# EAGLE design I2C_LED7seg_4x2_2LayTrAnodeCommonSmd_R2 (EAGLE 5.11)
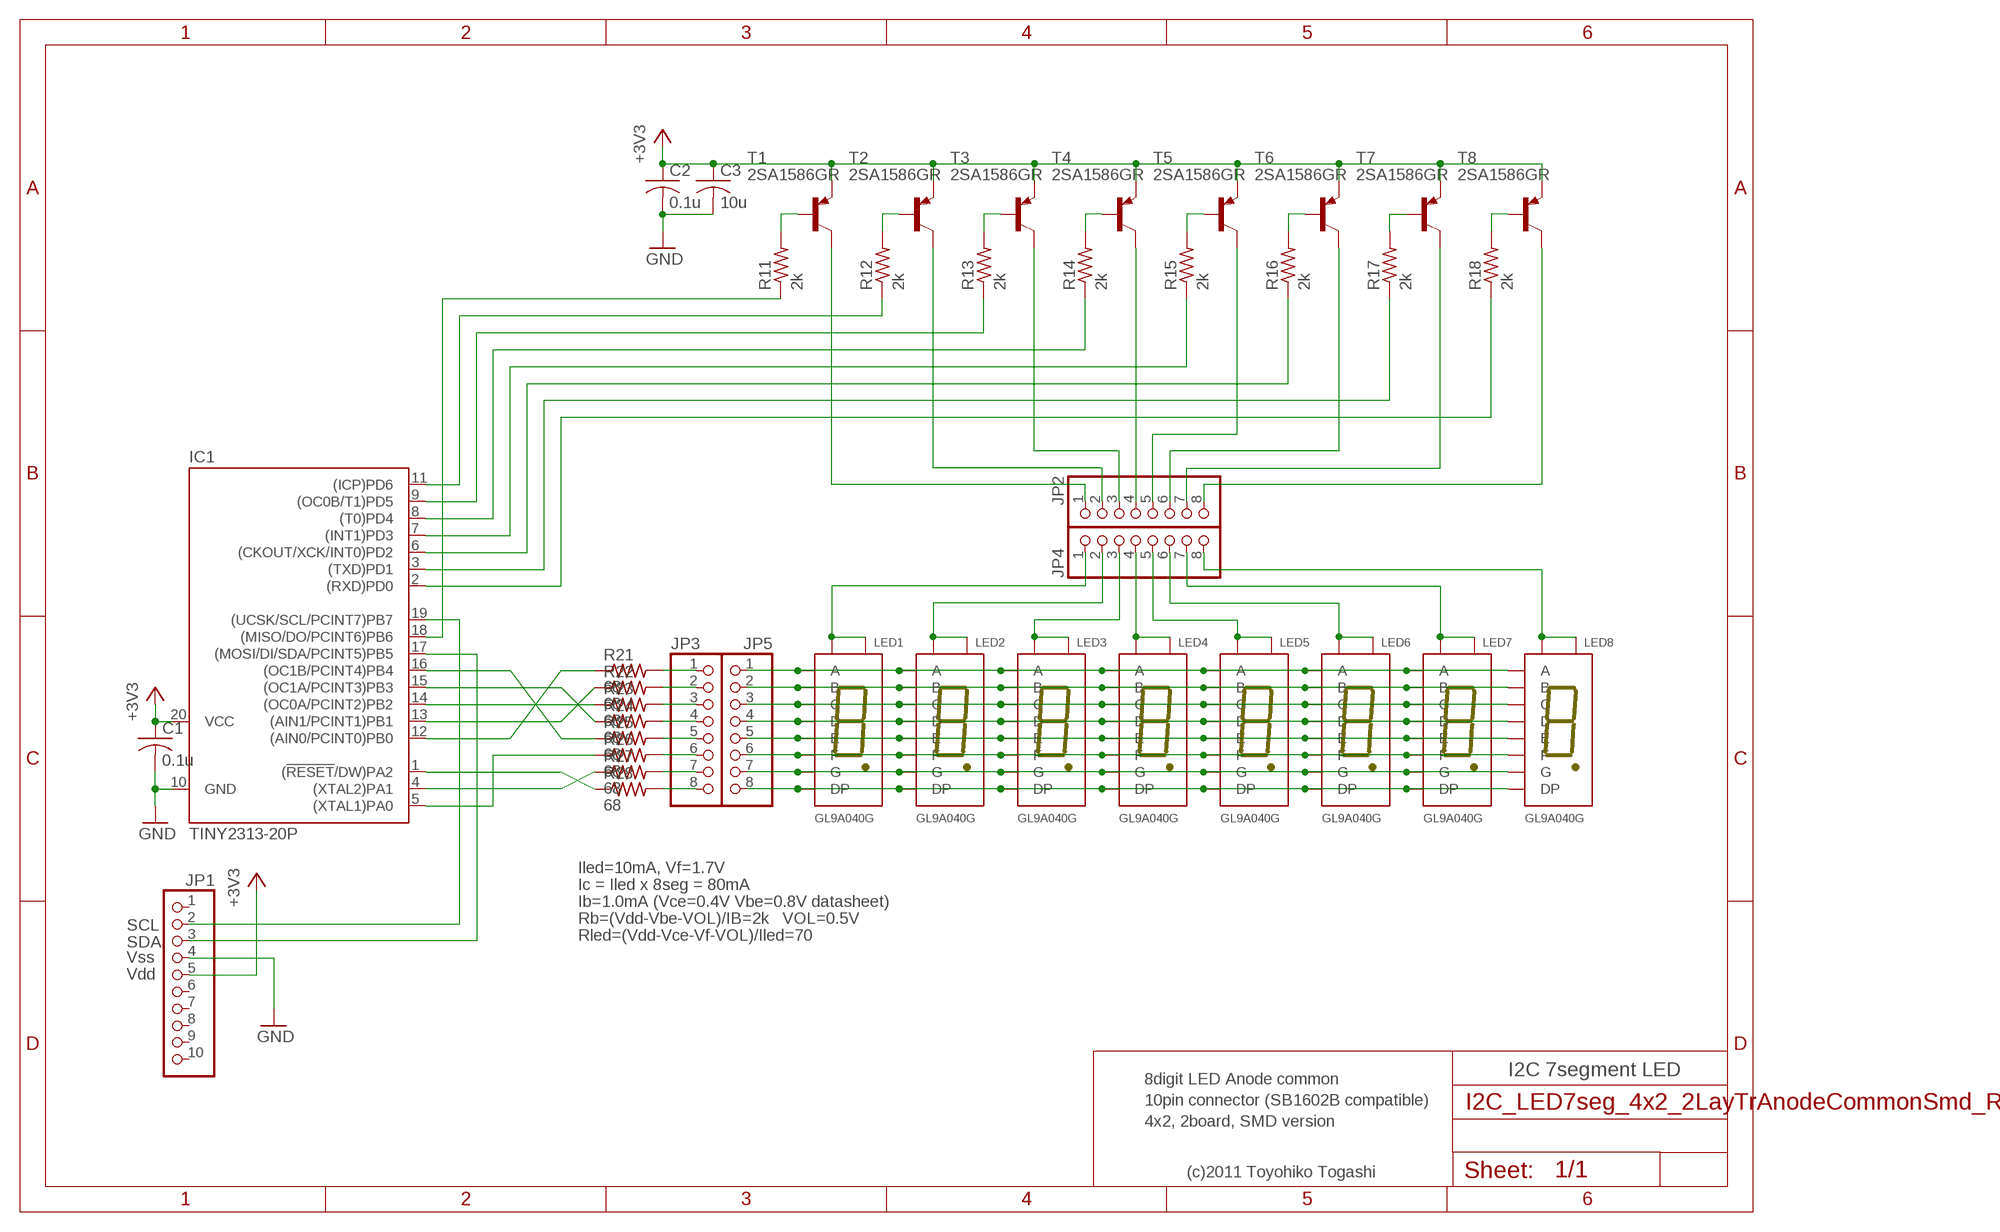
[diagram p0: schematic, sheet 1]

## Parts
C1  0.1u  C-USC0603  [C0603]
C2  0.1u  C-USC0603  [C0603]
C3  10u  C-USC1206  [C1206]
IC1  TINY2313-20P  [DIL20]
JP1  PINHD-1X10  [1X10]
JP2  PINHD-1X8  [1X08]
JP3  PINHD-1X8  [1X08]
JP4  PINHD-1X8  [1X08]
JP5  PINHD-1X8  [1X08]
LED1  GL9A040G  [GL9A040G]
LED2  GL9A040G  [GL9A040G]
LED3  GL9A040G  [GL9A040G]
LED4  GL9A040G  [GL9A040G]
LED5  GL9A040G  [GL9A040G]
LED6  GL9A040G  [GL9A040G]
LED7  GL9A040G  [GL9A040G]
LED8  GL9A040G  [GL9A040G]
R11  2k  R-US_R0603  [R0603]
R12  2k  R-US_R0603  [R0603]
R13  2k  R-US_R0603  [R0603]
R14  2k  R-US_R0603  [R0603]
R15  2k  R-US_R0603  [R0603]
R16  2k  R-US_R0603  [R0603]
R17  2k  R-US_R0603  [R0603]
R18  2k  R-US_R0603  [R0603]
R21  68  R-US_R0603  [R0603]
R22  68  R-US_R0603  [R0603]
R23  68  R-US_R0603  [R0603]
R24  68  R-US_R0603  [R0603]
R25  68  R-US_R0603  [R0603]
R26  68  R-US_R0603  [R0603]
R27  68  R-US_R0603  [R0603]
R28  68  R-US_R0603  [R0603]
T1  2SA1586GR  BC807-16LT1-PNP-SOT23-BEC  [SOT23-BEC]
T2  2SA1586GR  BC807-16LT1-PNP-SOT23-BEC  [SOT23-BEC]
T3  2SA1586GR  BC807-16LT1-PNP-SOT23-BEC  [SOT23-BEC]
T4  2SA1586GR  BC807-16LT1-PNP-SOT23-BEC  [SOT23-BEC]
T5  2SA1586GR  BC807-16LT1-PNP-SOT23-BEC  [SOT23-BEC]
T6  2SA1586GR  BC807-16LT1-PNP-SOT23-BEC  [SOT23-BEC]
T7  2SA1586GR  BC807-16LT1-PNP-SOT23-BEC  [SOT23-BEC]
T8  2SA1586GR  BC807-16LT1-PNP-SOT23-BEC  [SOT23-BEC]

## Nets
+3V3: C1.1 C2.1 C3.1 IC1.20(VCC) JP1.5 T1.E T2.E T3.E T4.E T5.E T6.E T7.E T8.E
GND: C1.2 C2.2 C3.2 IC1.10(GND) JP1.4
N$1: JP3.7 R27.2
N$2: JP3.8 R28.2
N$3: IC1.19((UCSK/SCL/PCINT7)PB7) JP1.2
N$4: IC1.17((MOSI/DI/SDA/PCINT5)PB5) JP1.3
N$5: JP3.1 R21.2
N$6: JP3.2 R22.2
N$7: JP3.3 R23.2
N$8: JP3.4 R24.2
N$9: JP3.5 R25.2
N$10: JP3.6 R26.2
N$11: JP2.1 T1.C
N$12: JP2.2 T2.C
N$13: R18.2 T8.B
N$14: IC1.5((XTAL1)PA0) R26.1
N$15: IC1.4((XTAL2)PA1) R27.1
N$16: IC1.1((!RESET!/DW)PA2) R28.1
N$17: IC1.12((AIN0/PCINT0)PB0) R21.1
N$18: JP4.1 LED1.P$1(CA1) LED1.P$6(CA6)
N$19: IC1.13((AIN1/PCINT1)PB1) R22.1
N$20: IC1.14((OC0A/PCINT2)PB2) R23.1
N$21: IC1.15((OC1A/PCINT3)PB3) R24.1
N$22: IC1.16((OC1B/PCINT4)PB4) R25.1
N$23: JP4.2 LED2.P$1(CA1) LED2.P$6(CA6)
N$24: JP4.3 LED3.P$1(CA1) LED3.P$6(CA6)
N$25: IC1.2((RXD)PD0) R18.1
N$26: R11.2 T1.B
N$27: JP4.4 LED4.P$1(CA1) LED4.P$6(CA6)
N$28: IC1.18((MISO/DO/PCINT6)PB6) R11.1
N$29: JP4.5 LED5.P$1(CA1) LED5.P$6(CA6)
N$30: JP4.6 LED6.P$1(CA1) LED6.P$6(CA6)
N$31: JP4.7 LED7.P$1(CA1) LED7.P$6(CA6)
N$32: JP4.8 LED8.P$1(CA1) LED8.P$6(CA6)
N$33: JP2.3 T3.C
N$34: JP2.4 T4.C
N$35: R17.2 T7.B
N$36: JP2.5 T5.C
N$37: JP2.6 T6.C
N$38: JP2.7 T7.C
N$39: JP2.8 T8.C
N$40: JP5.1 LED1.P$10(A) LED2.P$10(A) LED3.P$10(A) LED4.P$10(A) LED5.P$10(A) LED6.P$10(A) LED7.P$10(A) LED8.P$10(A)
N$41: JP5.2 LED1.P$9(B) LED2.P$9(B) LED3.P$9(B) LED4.P$9(B) LED5.P$9(B) LED6.P$9(B) LED7.P$9(B) LED8.P$9(B)
N$42: JP5.3 LED1.P$8(C) LED2.P$8(C) LED3.P$8(C) LED4.P$8(C) LED5.P$8(C) LED6.P$8(C) LED7.P$8(C) LED8.P$8(C)
N$43: JP5.4 LED1.P$5(D) LED2.P$5(D) LED3.P$5(D) LED4.P$5(D) LED5.P$5(D) LED6.P$5(D) LED7.P$5(D) LED8.P$5(D)
N$44: JP5.5 LED1.P$4(E) LED2.P$4(E) LED3.P$4(E) LED4.P$4(E) LED5.P$4(E) LED6.P$4(E) LED7.P$4(E) LED8.P$4(E)
N$45: JP5.6 LED1.P$2(F) LED2.P$2(F) LED3.P$2(F) LED4.P$2(F) LED5.P$2(F) LED6.P$2(F) LED7.P$2(F) LED8.P$2(F)
N$46: JP5.7 LED1.P$3(G) LED2.P$3(G) LED3.P$3(G) LED4.P$3(G) LED5.P$3(G) LED6.P$3(G) LED7.P$3(G) LED8.P$3(G)
N$47: JP5.8 LED1.P$7(DP) LED2.P$7(DP) LED3.P$7(DP) LED4.P$7(DP) LED5.P$7(DP) LED6.P$7(DP) LED7.P$7(DP) LED8.P$7(DP)
N$48: R16.2 T6.B
N$60: R15.2 T5.B
N$72: R14.2 T4.B
N$84: R13.2 T3.B
N$96: R12.2 T2.B
N$98: IC1.3((TXD)PD1) R17.1
N$99: IC1.6((CKOUT/XCK/INT0)PD2) R16.1
N$100: IC1.7((INT1)PD3) R15.1
N$101: IC1.8((T0)PD4) R14.1
N$102: IC1.9((OC0B/T1)PD5) R13.1
N$103: IC1.11((ICP)PD6) R12.1
Unconnected: JP1.1 JP1.6 JP1.7 JP1.8 JP1.9 JP1.10

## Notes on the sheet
- Iled=10mA, Vf=1.7V
- Ic = Iled x 8seg = 80mA
- Ib=1.0mA (Vce=0.4V Vbe=0.8V datasheet)
- Rb=(Vdd-Vbe-VOL)/IB=2k   VOL=0.5V
- SCL
- Rled=(Vdd-Vce-Vf-VOL)/Iled=70
- SDA
- Vss
- Vdd
- I2C 7segment LED
- 8digit LED Anode common
- 10pin connector (SB1602B compatible)
- 4x2, 2board, SMD version
- (c)2011 Toyohiko Togashi

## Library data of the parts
C1-C3 = rcl:C-US: CAPACITOR, American symbol
IC1 = TOG:TINY2313: 8-bit AVR Microcontroller with 2K Bytes Flash Source: http://www.atmel.com .. doc2543.pdf
JP1 = pinhead:PINHD-1X10: PIN HEADER
JP2-JP5 = pinhead:PINHD-1X8: PIN HEADER
LED1-LED8 = TOG:GL9A040G: 7 Segment LED
R11-R18 R21-R28 = rcl:R-US_: RESISTOR, American symbol
T1-T8 = transistor:*-PNP-: PNP Transistror

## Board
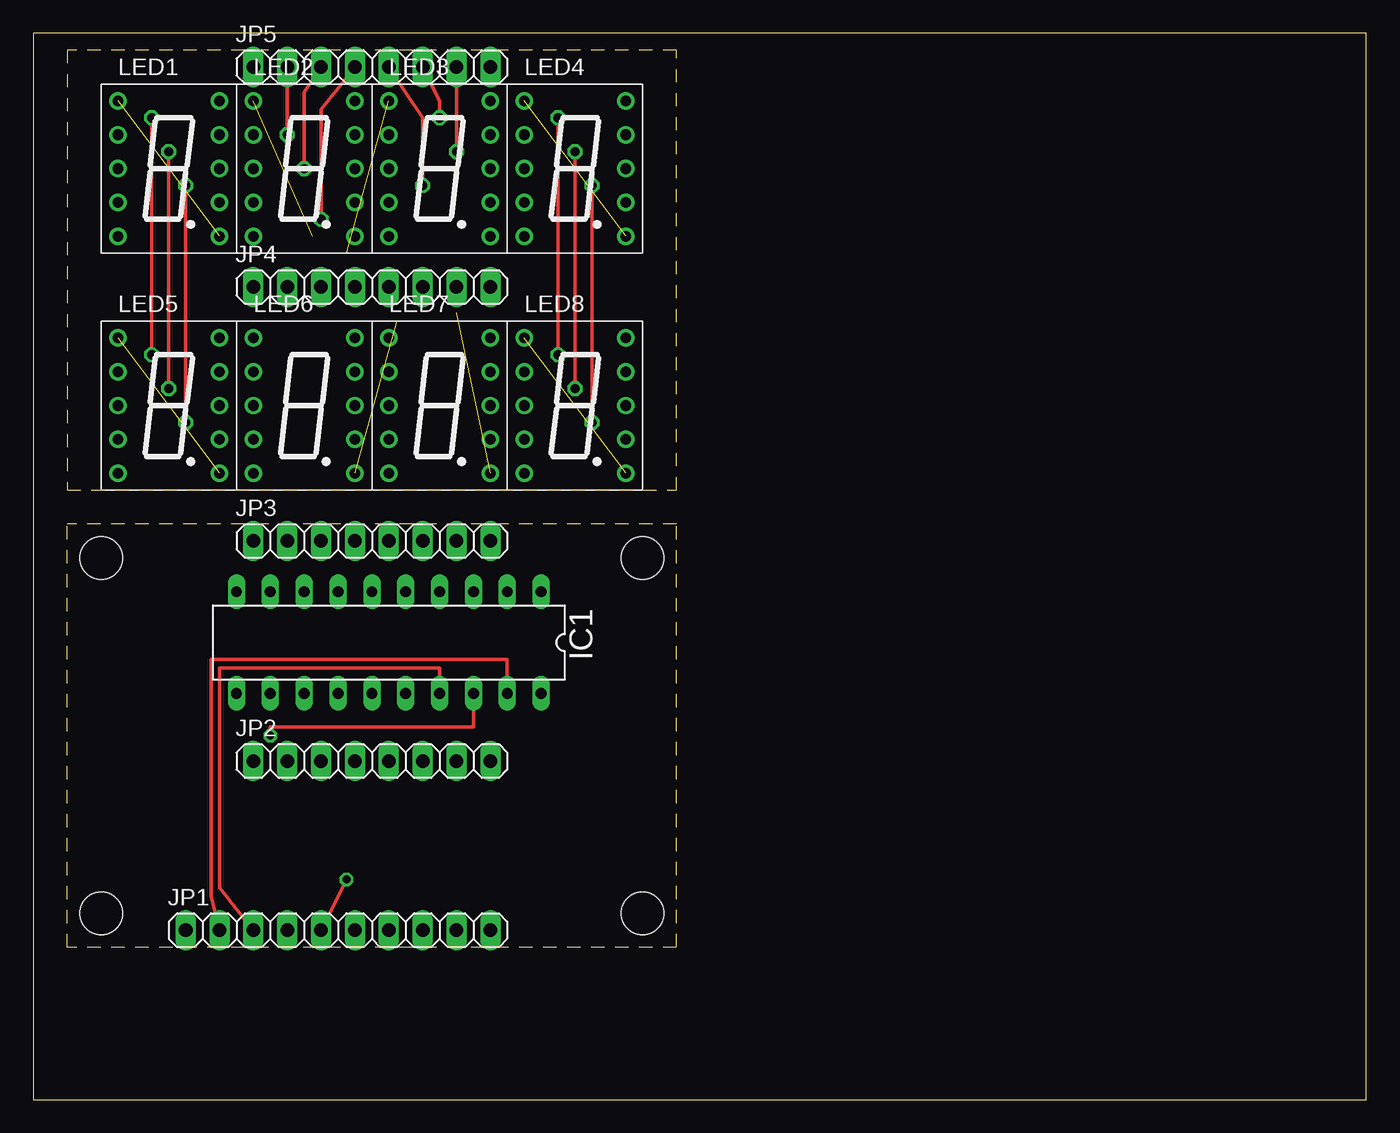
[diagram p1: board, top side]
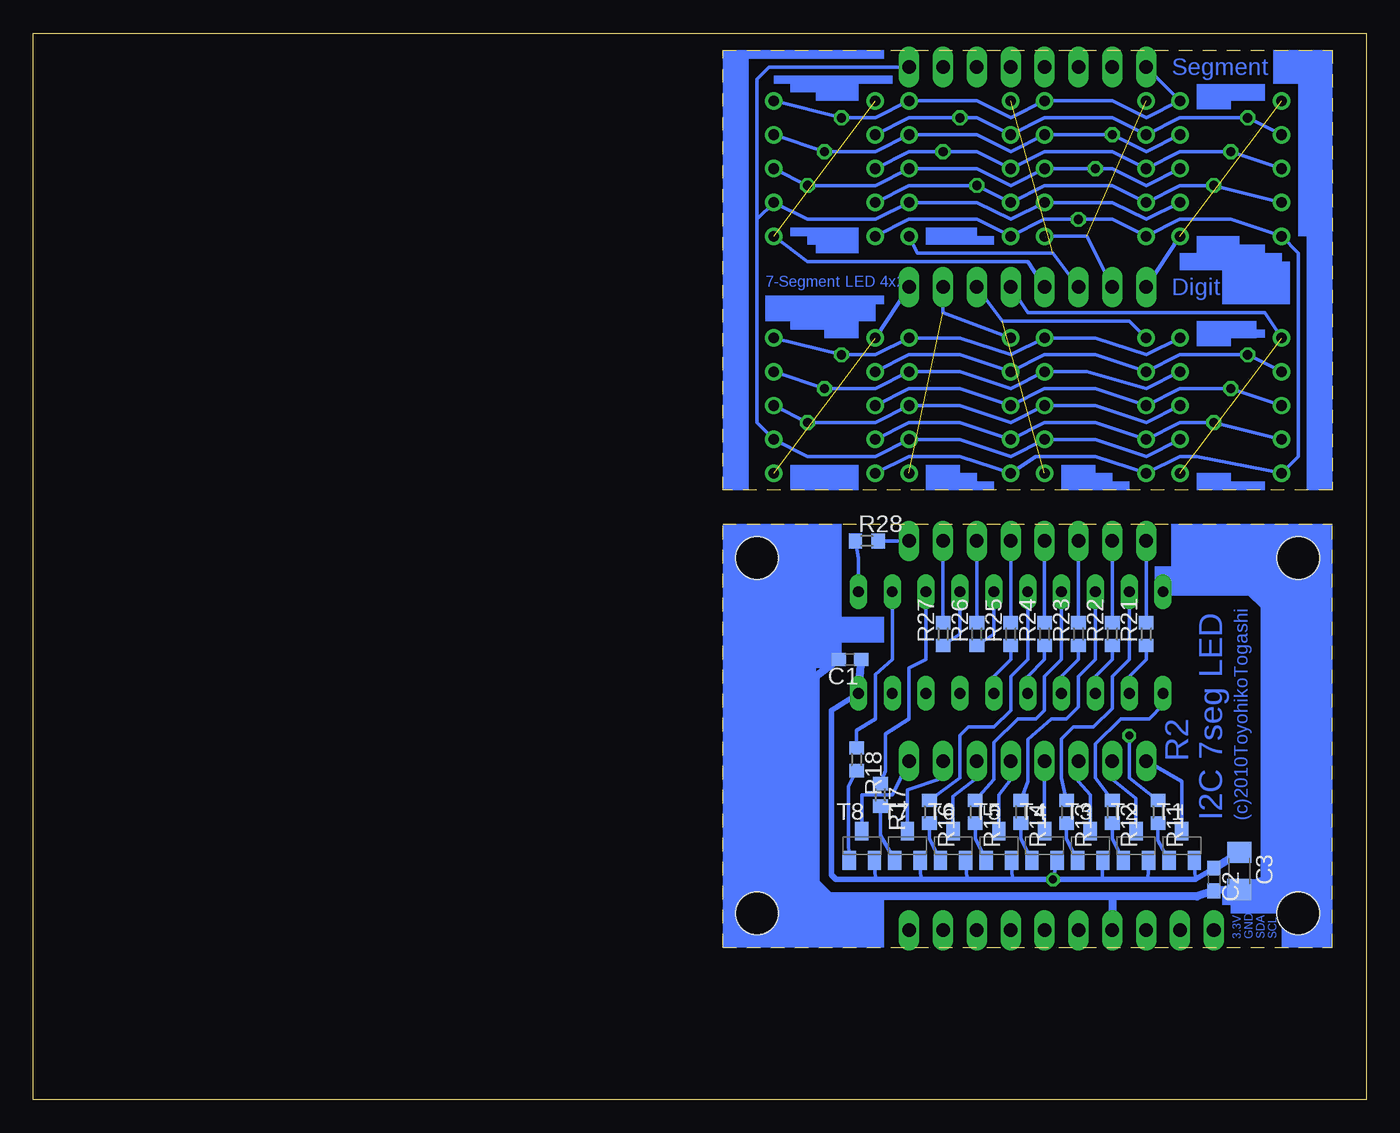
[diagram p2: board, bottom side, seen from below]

Size 100 x 80 mm. Coordinates in mm from the lower left corner, seen from the top.
Outline: 0,0 100,0 100,80 0,80 0,0
Outline: 2.54,78.74 2.54,45.72 48.26,45.72 48.26,78.74 2.54,78.74
Outline: 48.26,43.18 2.54,43.18 2.54,11.43 48.26,11.43 48.26,43.18
Copper layers (1*16): Top 0.035mm / dielectric 1.5mm / Bottom 0.035mm
Design rules "default": minimum track width 10mil, minimum drill 24mil, track to track 8mil, track to pad 8mil, pad to pad 8mil, via to via 8mil, smd to smd 8mil, copper to edge 40mil, drill to drill 8mil, minimum pad ring 10mil, minimum via ring 8mil, stop-mask expansion 4mil, vias tented up to drill 0mil, thermal gap 10mil
Holes 3.2 mm at 5.08,40.64 45.72,40.64 45.72,13.97 5.08,13.97

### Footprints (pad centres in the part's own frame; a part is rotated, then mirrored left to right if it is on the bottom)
C0603 = smd 1.1 x 1: 1 -0.85,0; 2 0.85,0
C1206 = smd 1.6 x 1.8: 1 -1.4,0; 2 1.4,0
DIL20 = drill 0.813 long: 1 -11.43,-3.81; 2 -8.89,-3.81; 3 -6.35,-3.81; 4 -3.81,-3.81; 5 -1.27,-3.81; 6 1.27,-3.81; 7 3.81,-3.81; 8 6.35,-3.81; 9 8.89,-3.81; 10 11.43,-3.81; 11 11.43,3.81; 12 8.89,3.81; 13 6.35,3.81; 14 3.81,3.81; 15 1.27,3.81; 16 -1.27,3.81; 17 -3.81,3.81; 18 -6.35,3.81; 19 -8.89,3.81; 20 -11.43,3.81
1X10 = drill 1.016 long: 1 -11.43,0; 2 -8.89,0; 3 -6.35,0; 4 -3.81,0; 5 -1.27,0; 6 1.27,0; 7 3.81,0; 8 6.35,0; 9 8.89,0; 10 11.43,0
1X08 = drill 1.016 long: 1 -8.89,0; 2 -6.35,0; 3 -3.81,0; 4 -1.27,0; 5 1.27,0; 6 3.81,0; 7 6.35,0; 8 8.89,0
GL9A040G = drill 0.8 round: P$1 -3.81,5.08; P$2 -3.81,2.54; P$3 -3.81,0; P$4 -3.81,-2.54; P$5 -3.81,-5.08; P$6 3.81,-5.08; P$7 3.81,-2.54; P$8 3.81,0; P$9 3.81,2.54; P$10 3.81,5.08
R0603 = smd 1 x 1.1: 1 -0.85,0; 2 0.85,0
SOT23-BEC = smd 1 x 1.4: B -0.95,-1.1; C 0,1.1; E 0.95,-1.1

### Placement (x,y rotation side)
C1  38.73,33.02 180 bottom
C2  11.43,16.51 270 bottom
C3  9.53,17.14 270 bottom
IC1  26.67,34.29 180 top
JP1  22.86,12.7 0 top
JP2  25.4,25.4 0 top
JP3  25.4,41.91 0 top
JP4  25.4,60.96 0 top
JP5  25.4,77.47 0 top
LED1  10.16,69.85 0 top
LED2  20.32,69.85 0 top
LED3  30.48,69.85 0 top
LED4  40.64,69.85 0 top
LED5  10.16,52.07 0 top
LED6  20.32,52.07 0 top
LED7  30.48,52.07 0 top
LED8  40.64,52.07 0 top
R11  15.62,21.59 270 bottom
R12  19.05,21.59 270 bottom
R13  22.48,21.59 270 bottom
R14  25.91,21.59 270 bottom
R15  29.34,21.59 270 bottom
R16  32.77,21.59 270 bottom
R17  36.45,22.86 270 bottom
R18  38.23,25.53 270 bottom
R21  16.51,34.92 90 bottom
R22  19.05,34.92 90 bottom
R23  21.59,34.92 90 bottom
R24  24.13,34.92 90 bottom
R25  26.67,34.92 90 bottom
R26  29.21,34.92 90 bottom
R27  31.75,34.92 90 bottom
R28  37.47,41.91 0 bottom
T1  13.84,19.05 0 bottom
T2  17.27,19.05 0 bottom
T3  20.7,19.05 0 bottom
T4  24.13,19.05 0 bottom
T5  27.56,19.05 0 bottom
T6  30.99,19.05 0 bottom
T7  34.42,19.05 0 bottom
T8  37.85,19.05 0 bottom

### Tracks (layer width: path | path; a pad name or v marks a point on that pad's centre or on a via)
+3V3  (via drill 0.6)
  Top 0.254: v23.5,16.51 JP1.5
  Bottom 0.254: 12.83,16.51 T1.E | 16.38,16.51 T2.E | 19.81,16.51 T3.E | v23.5,16.51 T4.E | 36.83,16.51 T8.E | 33.4,16.51 T7.E | 26.54,16.51 T5.E | 29.97,16.51 T6.E
  Bottom 0.406: IC1.20 40.13,29.21 40.13,16.87 39.77,16.51 36.83,16.51 33.4,16.51 29.97,16.51 26.54,16.51 v23.5,16.51 19.81,16.51 16.38,16.51 12.83,16.51 C2.1
  Bottom 0.61: IC1.20 C1.1 | C2.1 C3.1
GND
  Bottom 0.61: 19.05,15.24 40.25,15.24 41.27,16.26 41.27,31.75 C1.2 | 19.05,15.24 JP1.4 | IC1.10 8.7,38.1 7.62,37.02 7.62,16.51 C3.2 8.89,15.88 C2.2 12.7,15.24 19.05,15.24
N$1
  Bottom 0.254: JP3.7 R27.2
N$2
  Bottom 0.254: JP3.8 R28.2
N$3
  Top 0.254: JP1.2 13.34,15.24 13.34,33.02 35.56,33.02 IC1.19
N$4
  Top 0.254: JP1.3 13.97,15.88 13.97,32.38 30.48,32.38 IC1.17
N$5
  Bottom 0.254: JP3.1 R21.2
N$6
  Bottom 0.254: JP3.2 R22.2
N$7
  Bottom 0.254: JP3.3 R23.2
N$8
  Bottom 0.254: JP3.4 R24.2
N$9
  Bottom 0.254: JP3.5 R25.2
N$10
  Bottom 0.254: JP3.6 R26.2
N$11
  Bottom 0.254: T1.C 13.84,23.88 JP2.1
N$12
  Bottom 0.254: T2.C 17.27,22.61 19.05,24 JP2.2
N$13
  Bottom 0.254: T8.B 38.86,19.68 38.86,23.5 R18.2
N$14
  Bottom 0.254: IC1.5 27.94,34.92 R26.1
N$15
  Bottom 0.254: IC1.4 30.48,34.92 R27.1
N$16
  Bottom 0.254: R28.1 38.1,40.64 IC1.1
N$17
  Bottom 0.254: IC1.12 17.78,31.75 16.51,33.02 R21.1
N$18  (1 unrouted)
  Bottom 0.254: JP4.1 LED1.P$6
N$19
  Bottom 0.254: IC1.13 20.32,31.75 19.05,33.02 R22.1
N$20
  Bottom 0.254: IC1.14 22.86,31.75 21.59,33.02 R23.1
N$21
  Bottom 0.254: IC1.15 25.4,31.75 24.13,33.02 R24.1
N$22
  Bottom 0.254: IC1.16 27.94,31.75 26.67,33.02 R25.1
N$23  (1 unrouted)
  Bottom 0.254: JP4.2 20.95,64.77 LED2.P$6
N$24  (1 unrouted)
  Bottom 0.254: JP4.3 23.5,63.5 33.66,63.5 LED3.P$6
N$25
  Bottom 0.254: IC1.2 35.56,33.02 36.83,31.88 36.83,28.57 38.23,27.69 R18.1
N$26
  Bottom 0.254: T1.B 15.62,19.43 R11.2
N$27  (1 unrouted)
  Bottom 0.254: JP4.4 25.4,62.87 41.91,62.87 LED4.P$6
N$28  (via drill 0.6)
  Top 0.254: v17.78,27.3 17.78,27.94 33.02,27.94 IC1.18
  Bottom 0.254: R11.1 17.78,24.13 v17.78,27.3
N$29  (1 unrouted)
  Bottom 0.254: JP4.5 25.4,59.05 7.62,59.05 LED5.P$1
N$30  (1 unrouted)
  Bottom 0.254: JP4.6 27.3,58.42 17.78,58.42 LED6.P$1
N$31  (1 unrouted)
  Bottom 0.254: JP4.7 31.75,59.05 LED7.P$1
N$32  (1 unrouted)
  Bottom 0.254: LED8.P$1 JP4.8
N$33
  Bottom 0.254: T3.C 20.7,22.86 21.59,23.88 JP2.3
N$34
  Bottom 0.254: T4.C JP2.4
N$35
  Bottom 0.254: T7.B 36.45,19.81 R17.2
N$36
  Bottom 0.254: T5.C 27.56,22.86 26.67,24 JP2.5
N$37
  Bottom 0.254: T6.C 30.99,22.73 29.21,24.13 JP2.6
N$38
  Bottom 0.254: T7.C 34.42,23.24 31.75,24.13 JP2.7
N$39
  Bottom 0.254: T8.C 37.85,22.86 35.56,22.86 JP2.8
N$40  (via drill 0.7)
  Top 0.254: v39.37,55.88 v39.37,73.66
  Bottom 0.254: LED5.P$10 16.51,55.88 20.32,57.15 LED6.P$10 26.67,55.88 30.48,57.15 LED7.P$10 36.83,55.88 v39.37,55.88 LED8.P$10 | LED4.P$10 v39.37,73.66 36.83,73.66 LED3.P$10 29.21,74.93 26.67,73.66 LED2.P$10 19.05,74.93 16.51,73.66 LED1.P$10 JP5.1
N$41  (via drill 0.7)
  Top 0.254: v40.64,53.34 v40.64,71.12 | v19.05,72.39 JP5.2
  Bottom 0.254: LED5.P$9 16.51,53.34 20.95,54.61 LED6.P$9 26.67,53.34 30.48,54.61 LED7.P$9 36.83,53.34 v40.64,53.34 LED8.P$9 | LED1.P$9 16.51,71.12 v19.05,72.39 LED2.P$9 26.67,71.12 29.21,72.39 LED3.P$9 36.83,71.12 v40.64,71.12 LED4.P$9
N$42  (via drill 0.7)
  Top 0.254: v41.91,50.8 v41.91,68.58 | JP5.3 20.32,75.56 v20.32,69.85
  Bottom 0.254: LED5.P$8 16.51,50.8 20.32,52.07 LED6.P$8 26.67,50.8 30.48,52.07 LED7.P$8 36.83,50.8 v41.91,50.8 LED8.P$8 | LED1.P$8 16.51,68.58 19.05,69.85 v20.32,69.85 LED2.P$8 26.67,68.58 29.21,69.85 LED3.P$8 36.83,68.58 v41.91,68.58 LED4.P$8
N$43  (via drill 0.7)
  Top 0.254: JP5.4 21.59,74.3 v21.59,66.04
  Bottom 0.254: LED8.P$5 34.29,48.26 30.48,48.26 LED7.P$5 24.77,48.26 20.32,48.26 LED6.P$5 13.97,48.26 12.7,48.26 LED5.P$5 5.08,48.26 5.08,63.5 LED1.P$5 10.16,66.04 13.97,66.04 LED2.P$5 19.05,66.04 v21.59,66.04 24.13,66.04 LED3.P$5 29.21,66.04 34.29,66.04 LED4.P$5
N$44  (via drill 0.7)
  Top 0.254: v11.43,50.8 v11.43,68.58 | JP5.5 29.21,73.66 v29.21,68.58
  Bottom 0.254: LED8.P$4 34.29,50.8 30.48,50.8 LED7.P$4 24.13,50.8 20.32,50.8 LED6.P$4 13.97,50.8 v11.43,50.8 LED5.P$4 | LED4.P$4 34.29,68.58 v29.21,68.58 LED3.P$4 24.13,68.58 19.05,68.58 LED2.P$4 13.97,68.58 v11.43,68.58 LED1.P$4
N$45  (via drill 0.7)
  Top 0.254: v8.89,55.88 v8.89,73.66 | JP5.6 30.48,74.93 v30.48,73.66
  Bottom 0.254: LED8.P$2 34.29,55.88 30.48,55.88 LED7.P$2 24.13,55.88 20.32,55.88 LED6.P$2 13.97,55.88 v8.89,55.88 LED5.P$2 | LED4.P$2 34.29,73.66 v30.48,73.66 29.21,73.66 LED3.P$2 24.13,73.66 19.05,73.66 LED2.P$2 13.97,73.66 v8.89,73.66 LED1.P$2
N$46  (via drill 0.7)
  Top 0.254: v10.16,53.34 v10.16,71.12 | v31.75,71.12 JP5.7
  Bottom 0.254: LED8.P$3 34.29,53.34 30.48,53.34 LED7.P$3 24.13,53.34 20.32,53.34 LED6.P$3 13.97,53.34 v10.16,53.34 LED5.P$3 | LED4.P$3 34.29,71.12 v31.75,71.12 29.21,71.12 LED3.P$3 24.13,71.12 19.05,71.12 LED2.P$3 13.97,71.12 v10.16,71.12 LED1.P$3
N$47
  Bottom 0.254: LED5.P$7 16.51,48.26 20.32,49.53 LED6.P$7 26.67,48.26 30.48,49.53 LED7.P$7 36.83,48.26 41.91,48.26 LED8.P$7 45.72,50.8 45.72,66.04 | LED1.P$7 16.51,66.04 19.05,67.31 LED2.P$7 26.67,66.04 29.21,67.31 LED3.P$7 36.83,66.04 41.91,66.04 LED4.P$7 45.72,66.04 | 45.72,66.04 45.72,76.57 44.82,77.47 JP5.8
N$48
  Bottom 0.254: T6.B 32.77,19.56 R16.2
N$60
  Bottom 0.254: T5.B 29.34,19.56 R15.2
N$72
  Bottom 0.254: T4.B 25.91,19.56 R14.2
N$84
  Bottom 0.254: T3.B 22.48,19.56 R13.2
N$96
  Bottom 0.254: T2.B 19.05,19.56 R12.2
N$98
  Bottom 0.254: R17.1 36.07,24.64 36.07,27.43 34.29,28.57 34.29,32.38 33.02,33.02 IC1.3
N$99
  Bottom 0.254: R16.1 30.48,24.13 30.48,27.3 29.84,27.94 27.94,27.94 26.67,29.21 26.67,31.75 25.4,33.02 IC1.6
N$100
  Bottom 0.254: R15.1 27.94,24 27.94,26.78 26.14,28.57 24.77,28.57 24.13,29.21 24.13,31.75 22.86,33.02 IC1.7
N$101
  Bottom 0.254: R14.1 25.4,23.88 25.4,27.03 23.6,28.57 22.49,28.57 21.59,29.47 21.59,31.75 20.32,33.02 IC1.8
N$102
  Bottom 0.254: R13.1 22.86,24.13 22.86,27.04 21.96,27.94 20.47,27.94 19.05,29.36 19.05,31.75 17.78,33.02 IC1.9
N$103
  Bottom 0.254: R12.1 20.32,24.13 20.32,26.67 18.41,28.57 16.26,28.57 15.24,29.59 IC1.11
(copper drawn outside any net)
  shapes: Bottom area x67

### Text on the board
Bottom: Segment | 7-Segment LED 4x2 | Digit | R2 | (c)2010ToyohikoTogashi | I2C 7seg LED | SCL | SDA | GND | 3.3V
